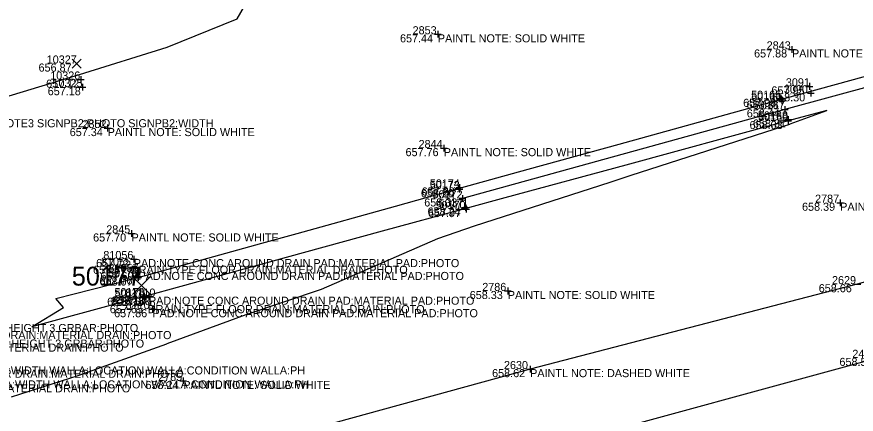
# Model space of a CAD drawing. Extents: x 2129350 to 2137777, y 657588 to 659885.
# Drawn here: x 2132608.9 to 2132733.5, y 658614.9 to 658674 of the extents above; entities that cross this region are included whole.
import ezdxf

# ---------------------------------------------------------------- set-up
doc = ezdxf.new("R2010")
doc.units = 0
for name, color, linetype in [('BR_X_SV_Abut_Text', 7, 'Continuous'), ('DT_X_Contour_Minor', 7, 'Continuous'), ('GK_Visualization', 7, 'Continuous'), ('PV_X_COP', 7, 'Continuous'), ('SV_X_Random_Point', 7, 'Continuous'), ('SV_X_Shot_Marker', 7, 'Continuous'), ('SV_X_Text_Comment', 7, 'Continuous'), ('SV_X_Text_Elevation', 7, 'Continuous'), ('SV_X_Text_Name', 7, 'Continuous')]:
    doc.layers.add(name, color=color, linetype=linetype)

msp = doc.modelspace()

# ---------------------------------------------------------------- linework, layer by layer
at = {"layer": 'DT_X_Contour_Minor'}
for points in [[(2132599.35, 658659.73), (2132618.15, 658665.42), (2132631.19, 658669.46), (2132641.56, 658673.65), (2132643.96, 658677.83)], [(2132608.07, 658617.52), (2132617.99, 658620.71), (2132631.12, 658625.42), (2132631.19, 658625.44), (2132642.92, 658629.75), (2132654.12, 658633.54), (2132671.39, 658641.02), (2132676.83, 658642.93), (2132676.83, 658642.93), (2132696.97, 658649.43), (2132700.1, 658650.43), (2132722.71, 658657.74), (2132723.66, 658658.04), (2132723.69, 658658.05), (2132729.15, 658660.07), (2132723.41, 658658.51), (2132722.09, 658658.15), (2132699.29, 658651.95), (2132681.33, 658647.06), (2132675.53, 658645.49), (2132663.11, 658642.11), (2132651.4, 658638.9), (2132644.02, 658636.89), (2132627.8, 658632.44), (2132624.89, 658631.67), (2132611.09, 658627.92), (2132615.81, 658630.78), (2132614.67, 658632.13), (2132625.52, 658634.91), (2132626.89, 658635.26), (2132645.26, 658640.34), (2132650.49, 658641.8), (2132665.07, 658645.84), (2132674.59, 658648.5), (2132684.81, 658651.32), (2132698.29, 658655.06), (2132717.39, 658660.36), (2132722.38, 658661.74), (2132726.05, 658662.75), (2132741.02, 658666.84)]]:
    msp.add_lwpolyline(points, dxfattribs=at)
at = {"layer": 'GK_Visualization'}
for p, q in [((2132626.04, 658632.72), (2132628.7, 658635.39)), ((2132626.04, 658635.39), (2132628.7, 658632.72))]:
    msp.add_line(p, q, dxfattribs=at)
at = {"layer": 'PV_X_COP'}
for points in [[(2133730.22, 658936.63), (2133702.62, 658928.99), (2133654.91, 658915.86), (2133605.08, 658902.34), (2133554.92, 658888.56), (2133509.82, 658876.27), (2133459.08, 658862.07), (2133410.5, 658848.76), (2133362.33, 658835.49), (2133317.19, 658823.07), (2133266.35, 658808.95), (2133217.78, 658795.57), (2133170.89, 658782.95), (2133115.31, 658767.84), (2133063.51, 658753.59), (2133014.74, 658740.25), (2132963.88, 658726.32), (2132916.79, 658713.58), (2132868.39, 658700.1), (2132821.62, 658687.28), (2132770.55, 658673.15), (2132722.89, 658660.22), (2132675.02, 658647)], [(2132158.56, 658463.82), (2132206.06, 658477.43), (2132254.46, 658490.67), (2132302.65, 658503.88), (2132350.77, 658517.2), (2132399.19, 658530.48), (2132447.47, 658543.51), (2132495.63, 658557.08), (2132543.81, 658570.09), (2132591.55, 658583.09), (2132640.05, 658596.45), (2132688.42, 658610.15), (2132736.65, 658623.32), (2132784.37, 658636.37), (2132832.92, 658649.95), (2132881.17, 658663.77), (2132929.56, 658676.42), (2132976.85, 658690.09), (2133025.73, 658703.1), (2133073.54, 658716.2), (2133122.49, 658729.47), (2133170.2, 658742.4), (2133218.35, 658756.09)], [(2132830.06, 658661.48), (2132781.46, 658647.76), (2132733.66, 658634.26), (2132685.08, 658621.65), (2132636.78, 658608.37), (2132588.98, 658595.34), (2132540.41, 658581.57), (2132492.62, 658568.33), (2132444.23, 658554.78), (2132396.24, 658542.04), (2132348.05, 658529.35), (2132299.13, 658515.13), (2132251.46, 658501.25), (2132202.83, 658488.38), (2132155.56, 658475.63)]]:
    msp.add_lwpolyline(points, dxfattribs=at)
at = {"layer": 'SV_X_Random_Point'}
for p, q in [((2132617.08, 658666.36), (2132618.41, 658667.7)), ((2132617.08, 658667.7), (2132618.41, 658666.36))]:
    msp.add_line(p, q, dxfattribs=at)
at = {"layer": 'SV_X_Shot_Marker'}
for p, q in [((2132670.88, 658671.37), (2132671.88, 658671.37)), ((2132671.38, 658671.87), (2132671.38, 658670.87)), ((2132671.38, 658671.37), (2132671.38, 658671.37)), ((2132723.96, 658669.63), (2132723.96, 658668.63)), ((2132723.46, 658669.13), (2132724.46, 658669.13)), ((2132723.96, 658669.13), (2132723.96, 658669.13)), ((2132617.85, 658664.65), (2132618.85, 658664.65)), ((2132618.35, 658665.15), (2132618.35, 658664.15)), ((2132618.35, 658664.65), (2132618.35, 658664.65)), ((2132618.11, 658663.52), (2132619.11, 658663.52)), ((2132618.61, 658664.02), (2132618.61, 658663.02)), ((2132618.61, 658663.52), (2132618.61, 658663.52)), ((2132726.04, 658663.64), (2132727.04, 658663.64)), ((2132726.54, 658664.14), (2132726.54, 658663.14)), ((2132726.54, 658663.64), (2132726.54, 658663.64)), ((2132722.36, 658662.29), (2132722.36, 658661.29)), ((2132726.27, 658662.61), (2132727.27, 658662.61)), ((2132726.77, 658663.11), (2132726.77, 658662.11)), ((2132726.77, 658662.61), (2132726.77, 658662.61)), ((2132721.86, 658661.79), (2132722.86, 658661.79)), ((2132721.95, 658661.51), (2132722.95, 658661.51)), ((2132722.36, 658661.79), (2132722.36, 658661.79)), ((2132722.45, 658662.01), (2132722.45, 658661.01)), ((2132722.45, 658661.51), (2132722.45, 658661.51)), ((2132722.39, 658660.22), (2132723.39, 658660.22)), ((2132722.89, 658660.72), (2132722.89, 658659.72)), ((2132722.89, 658660.22), (2132722.89, 658660.22)), ((2132722.88, 658658.73), (2132723.88, 658658.73)), ((2132722.91, 658658.5), (2132723.91, 658658.5)), ((2132723.38, 658659.23), (2132723.38, 658658.23)), ((2132723.38, 658658.73), (2132723.38, 658658.73)), ((2132723.41, 658659), (2132723.41, 658658)), ((2132723.41, 658658.5), (2132723.41, 658658.5)), ((2132621.85, 658657.45), (2132622.85, 658657.45)), ((2132622.35, 658657.95), (2132622.35, 658656.95)), ((2132622.35, 658657.45), (2132622.35, 658657.45)), ((2132672.26, 658654.97), (2132672.26, 658653.97)), ((2132671.76, 658654.47), (2132672.76, 658654.47)), ((2132672.26, 658654.47), (2132672.26, 658654.47)), ((2132674.09, 658648.37), (2132675.09, 658648.37)), ((2132674.1, 658648.63), (2132675.1, 658648.63)), ((2132674.59, 658648.87), (2132674.59, 658647.87)), ((2132674.59, 658648.37), (2132674.59, 658648.37)), ((2132674.6, 658649.13), (2132674.6, 658648.13)), ((2132674.6, 658648.63), (2132674.6, 658648.63)), ((2132675.02, 658647.5), (2132675.02, 658646.5)), ((2132674.52, 658647), (2132675.52, 658647)), ((2132675.02, 658647), (2132675.02, 658647)), ((2132675.46, 658646.16), (2132675.46, 658645.16)), ((2132675.56, 658645.92), (2132675.56, 658644.92)), ((2132730.62, 658646.36), (2132731.62, 658646.36)), ((2132731.12, 658646.86), (2132731.12, 658645.86)), ((2132731.12, 658646.36), (2132731.12, 658646.36)), ((2132674.96, 658645.66), (2132675.96, 658645.66)), ((2132675.06, 658645.42), (2132676.06, 658645.42)), ((2132675.46, 658645.66), (2132675.46, 658645.66)), ((2132675.56, 658645.42), (2132675.56, 658645.42)), ((2132625.9, 658642.3), (2132625.9, 658641.3)), ((2132625.4, 658641.8), (2132626.4, 658641.8)), ((2132625.9, 658641.8), (2132625.9, 658641.8)), ((2132626.24, 658638.49), (2132626.24, 658637.49)), ((2132625.74, 658637.99), (2132626.74, 658637.99)), ((2132626.24, 658637.99), (2132626.24, 658637.99)), ((2132626.43, 658636.08), (2132627.43, 658636.08)), ((2132626.85, 658635.92), (2132626.85, 658634.92)), ((2132626.93, 658636.58), (2132626.93, 658635.58)), ((2132626.93, 658636.08), (2132626.93, 658636.08)), ((2132626.35, 658635.42), (2132627.35, 658635.42)), ((2132626.39, 658635.25), (2132627.39, 658635.25)), ((2132626.85, 658635.42), (2132626.85, 658635.42)), ((2132626.89, 658635.75), (2132626.89, 658634.75)), ((2132626.89, 658635.25), (2132626.89, 658635.25)), ((2132681.77, 658633.75), (2132681.77, 658632.75)), ((2132733.16, 658634.26), (2132734.16, 658634.26)), ((2132627.29, 658632.48), (2132628.29, 658632.48)), ((2132627.38, 658632.26), (2132628.38, 658632.26)), ((2132627.79, 658632.98), (2132627.79, 658631.98)), ((2132627.79, 658632.48), (2132627.79, 658632.48)), ((2132627.88, 658632.76), (2132627.88, 658631.76)), ((2132627.88, 658632.26), (2132627.88, 658632.26)), ((2132627.98, 658632.41), (2132628.98, 658632.41)), ((2132628.48, 658632.91), (2132628.48, 658631.91)), ((2132628.48, 658632.41), (2132628.48, 658632.41)), ((2132681.27, 658633.25), (2132682.27, 658633.25)), ((2132681.77, 658633.25), (2132681.77, 658633.25)), ((2132629, 658631.05), (2132629, 658630.05)), ((2132628.5, 658630.55), (2132629.5, 658630.55)), ((2132629, 658630.55), (2132629, 658630.55)), ((2132684.58, 658621.65), (2132685.58, 658621.65)), ((2132685.08, 658622.15), (2132685.08, 658621.15)), ((2132685.08, 658621.65), (2132685.08, 658621.65)), ((2132633.08, 658619.89), (2132634.08, 658619.89)), ((2132633.58, 658620.39), (2132633.58, 658619.39)), ((2132633.58, 658619.89), (2132633.58, 658619.89))]:
    msp.add_line(p, q, dxfattribs=at)

# ---------------------------------------------------------------- texts
at = {"layer": 'BR_X_SV_Abut_Text'}
for p in [(2132578.28, 658620.85), (2132578.89, 658618.78)]:
    msp.add_text('WALLA:MATERIAL CONCRETE WALLA:WIDTH WALLA:LOCATION WALLA:CONDITION WALLA:PH', height=1.2, dxfattribs=at).set_placement(p)
at = {"layer": 'GK_Visualization'}
msp.add_text('50177', height=2.8, dxfattribs=at).set_placement((2132617.03, 658634.05))
at = {"layer": 'SV_X_Text_Comment'}
for s, p in [('PAINTL NOTE: SOLID WHITE', (2132671.38, 658670.17)), ('PAINTL NOTE: SOLID WHITE', (2132723.96, 658667.93)), ('SIGNPB2:NOTE1 25 SIGNPB2:NOTE2 SIGNPB2:NOTE3 SIGNPB2:PHOTO SIGNPB2:WIDTH', (2132570.03, 658657.56)), ('PAINTL NOTE: SOLID WHITE', (2132622.35, 658656.25)), ('PAINTL NOTE: SOLID WHITE', (2132672.26, 658653.27)), ('PAINTL NOTE: SOLID WHITE', (2132731.12, 658645.16)), ('PAINTL NOTE: SOLID WHITE', (2132625.9, 658640.6)), ('PAD:NOTE CONC AROUND DRAIN PAD:MATERIAL PAD:PHOTO', (2132626.24, 658636.79)), ('DRAIN:TYPE FLOOR DRAIN:MATERIAL DRAIN:PHOTO', (2132625.8, 658635.8)), ('PAD:NOTE CONC AROUND DRAIN PAD:MATERIAL PAD:PHOTO', (2132626.93, 658634.88)), ('PAD:NOTE CONC AROUND DRAIN PAD:MATERIAL PAD:PHOTO', (2132628.48, 658631.21)), ('PAINTL NOTE: SOLID WHITE', (2132681.77, 658632.05)), ('DRAIN:TYPE FLOOR DRAIN:MATERIAL DRAIN:PHOTO', (2132628.31, 658629.95)), ('PAD:NOTE CONC AROUND DRAIN PAD:MATERIAL PAD:PHOTO', (2132629, 658629.35)), ('DRAIN:TYPE FLOOR DRAIN:MATERIAL DRAIN:PHOTO', (2132590.72, 658626.1)), ('GRBAR:HEIGHT 3 GRBAR:PHOTO', (2132601.03, 658627.15)), ('GRBAR:HEIGHT 3 GRBAR:PHOTO', (2132601.91, 658624.84)), ('DRAIN:TYPE FLOOR DRAIN:MATERIAL DRAIN:PHOTO', (2132583.62, 658624.24)), ('DRAIN:TYPE FLOOR DRAIN:MATERIAL DRAIN:PHOTO', (2132592.49, 658620.36)), ('PAINTL NOTE: DASHED WHITE', (2132685.08, 658620.45)), ('PAINTL NOTE: SOLID WHITE', (2132633.58, 658618.69)), ('DRAIN:TYPE FLOOR DRAIN:MATERIAL DRAIN:PHOTO', (2132584.6, 658618.19))]:
    msp.add_text(s, height=1.2, dxfattribs=at).set_placement(p)
at = {"layer": 'SV_X_Text_Elevation'}
for s, p in [('657.44', (2132665.76, 658670.17)), ('657.88', (2132718.33, 658667.93)), ('656.87', (2132612.09, 658665.83)), ('657.12', (2132613.21, 658663.44)), ('657.18', (2132613.45, 658662.32)), ('657.95', (2132720.9, 658662.44)), ('658.30', (2132721.01, 658661.41)), ('657.98', (2132716.71, 658660.59)), ('658.31', (2132717.22, 658660.31)), ('658.44', (2132717.25, 658659.03)), ('658.03', (2132717.66, 658657.3)), ('658.31', (2132718.16, 658657.53)), ('657.34', (2132616.72, 658656.25)), ('657.76', (2132666.58, 658653.27)), ('658.20', (2132668.86, 658647.17)), ('657.88', (2132668.97, 658647.43)), ('658.33', (2132669.36, 658645.8)), ('658.39', (2132725.45, 658645.16)), ('658.24', (2132669.85, 658644.45)), ('657.97', (2132669.92, 658644.22)), ('657.70', (2132620.19, 658640.6)), ('657.72', (2132620.64, 658636.79)), ('657.57', (2132620.18, 658635.8)), ('657.69', (2132621.28, 658634.88)), ('658.07', (2132621.14, 658634.05)), ('657.70', (2132621.15, 658634.22)), ('658.66', (2132727.93, 658633.06)), ('657.75', (2132622.28, 658631.06)), ('657.78', (2132622.86, 658631.21)), ('658.11', (2132623.05, 658631.29)), ('658.33', (2132676.11, 658632.05)), ('657.65', (2132622.67, 658629.95)), ('657.86', (2132623.31, 658629.35)), ('658.53', (2132731.01, 658622.12)), ('658.62', (2132679.43, 658620.45)), ('658.24', (2132627.97, 658618.69))]:
    msp.add_text(s, height=1.2, dxfattribs=at).set_placement(p)
at = {"layer": 'SV_X_Text_Name'}
for s, p in [('2853', (2132667.63, 658671.37)), ('2843', (2132720.2, 658669.13)), ('10327', (2132613.3, 658667.03)), ('10326', (2132613.82, 658664.65)), ('10325', (2132614.16, 658663.52)), ('3091', (2132723.05, 658663.64)), ('3090', (2132722.75, 658662.61)), ('50165', (2132717.89, 658661.79)), ('50166', (2132717.9, 658661.51)), ('50167', (2132718.42, 658660.22)), ('50168', (2132718.9, 658658.73)), ('50169', (2132718.94, 658658.5)), ('2852', (2132618.61, 658657.45)), ('2844', (2132668.51, 658654.47)), ('50174', (2132670.18, 658648.63)), ('50173', (2132670.16, 658648.37)), ('50172', (2132670.59, 658647)), ('2787', (2132727.39, 658646.36)), ('50170', (2132671.03, 658645.42)), ('50171', (2132671.46, 658645.66)), ('2845', (2132622.14, 658641.8)), ('81056', (2132621.71, 658637.99)), ('81055', (2132621.35, 658637.01)), ('81057', (2132622.48, 658636.08)), ('50176', (2132622.39, 658635.25)), ('50175', (2132622.42, 658635.42)), ('2629', (2132729.9, 658634.26)), ('50178', (2132623.35, 658632.48)), ('50179', (2132623.44, 658632.26)), ('81110', (2132624.98, 658632.41)), ('2786', (2132677.97, 658633.25)), ('81108', (2132624.32, 658631.15)), ('81109', (2132625.02, 658630.55)), ('2424', (2132732.92, 658623.32)), ('2630', (2132681.19, 658621.65)), ('2785', (2132629.85, 658619.89))]:
    msp.add_text(s, height=1.2, dxfattribs=at).set_placement(p)

doc.saveas('drawing.dxf')
